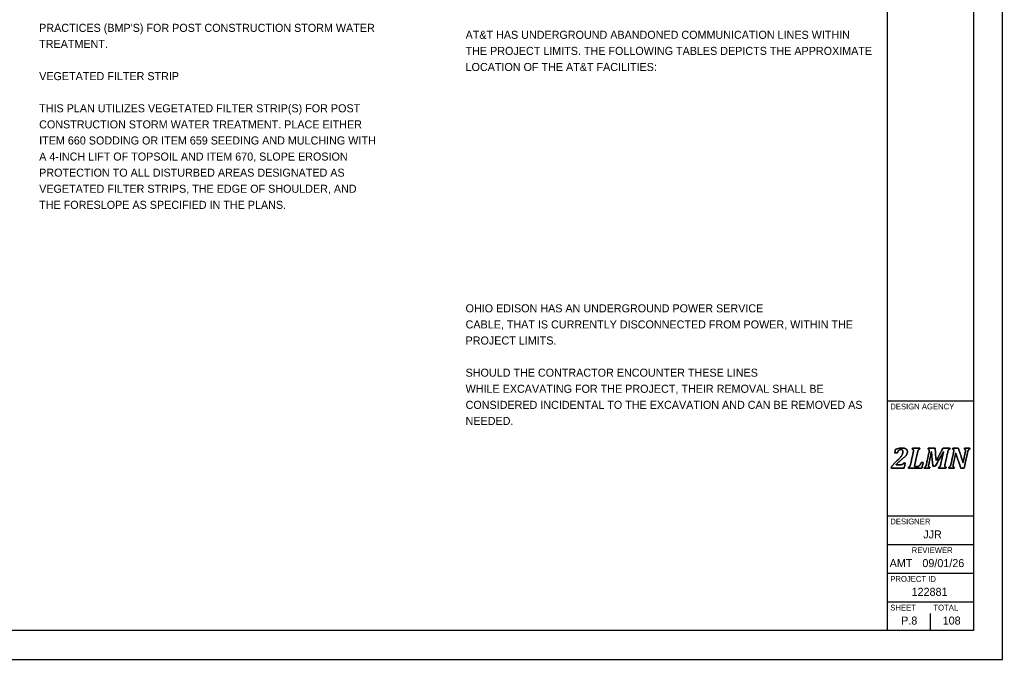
# Model space of a CAD drawing. Extents: x 0 to 34, y 0 to 22.
# Drawn here: x 16.9 to 34, y 0 to 11.13 of the extents above; entities that cross this region are included whole.
import ezdxf

# ---------------------------------------------------------------- set-up
doc = ezdxf.new("R2010")
doc.units = 0
for name, color, linetype in [('SH_Border', 7, 'Continuous'), ('SH_Cut_Line', 7, 'Continuous'), ('SH_Data', 7, 'Continuous'), ('SH_Text', 7, 'Continuous')]:
    doc.layers.add(name, color=color, linetype=linetype)

msp = doc.modelspace()

# ---------------------------------------------------------------- linework, layer by layer
at = {"layer": 'SH_Border'}
for p, q in [((32, 0.5), (32, 21.5)), ((32, 4.5), (33.5, 4.5)), ((32, 2.5), (33.5, 2.5)), ((32, 2), (33.5, 2)), ((32, 1.5), (33.5, 1.5)), ((32, 1), (33.5, 1))]:
    msp.add_line(p, q, dxfattribs=at)
msp.add_lwpolyline([(1.5, 21.5), (33.5, 21.5), (33.5, 0.5), (1.5, 0.5)], close=True, dxfattribs=at)
at = {"layer": 'SH_Cut_Line'}
msp.add_lwpolyline([(0, 0), (34, 0), (34, 22), (0, 22)], close=True, dxfattribs=at)
at = {"layer": 'SH_Data'}
for p, q in [((32.75, 3.5), (32.75, 3.5)), ((32.75, 0.5), (32.75, 0.8)), ((32.375, 0.675), (32.375, 0.675))]:
    msp.add_line(p, q, dxfattribs=at)
for points in [[(32.237, 3.388), (32.246, 3.388), (32.253, 3.389), (32.258, 3.39), (32.263, 3.392), (32.267, 3.394), (32.27, 3.397), (32.273, 3.401), (32.277, 3.408), (32.281, 3.417), (32.281, 3.417), (32.312, 3.417), (32.312, 3.417), (32.312, 3.417), (32.29, 3.326), (32.29, 3.326), (32.29, 3.326), (32.066, 3.326), (32.066, 3.326), (32.066, 3.326), (32.069, 3.343), (32.069, 3.343), (32.078, 3.358), (32.091, 3.375), (32.106, 3.394), (32.122, 3.412), (32.144, 3.435), (32.172, 3.462), (32.197, 3.486), (32.217, 3.506), (32.23, 3.521), (32.243, 3.537), (32.253, 3.551), (32.259, 3.566), (32.266, 3.58), (32.269, 3.595), (32.269, 3.61), (32.269, 3.622), (32.266, 3.632), (32.26, 3.64), (32.253, 3.647), (32.245, 3.65), (32.234, 3.65), (32.22, 3.65), (32.208, 3.646), (32.198, 3.636), (32.188, 3.627), (32.18, 3.613), (32.172, 3.593), (32.172, 3.593), (32.126, 3.593), (32.126, 3.593), (32.126, 3.593), (32.14, 3.654), (32.14, 3.654), (32.166, 3.663), (32.188, 3.669), (32.205, 3.673), (32.223, 3.676), (32.24, 3.678), (32.258, 3.678), (32.278, 3.678), (32.295, 3.675), (32.309, 3.669), (32.322, 3.664), (32.332, 3.656), (32.339, 3.646), (32.345, 3.637), (32.348, 3.626), (32.348, 3.613), (32.348, 3.602), (32.346, 3.591), (32.342, 3.581), (32.339, 3.571), (32.333, 3.56), (32.324, 3.549), (32.315, 3.539), (32.304, 3.526), (32.289, 3.513), (32.275, 3.499), (32.254, 3.482), (32.228, 3.46), (32.216, 3.45), (32.202, 3.438), (32.188, 3.425), (32.174, 3.412), (32.162, 3.4), (32.154, 3.391), (32.154, 3.391), (32.153, 3.388), (32.153, 3.388), (32.153, 3.388), (32.237, 3.388), (32.237, 3.388)], [(32.237, 3.388), (32.237, 3.388), (32.153, 3.388), (32.153, 3.388), (32.153, 3.388), (32.154, 3.391), (32.154, 3.391), (32.162, 3.4), (32.174, 3.412), (32.188, 3.425), (32.202, 3.438), (32.216, 3.45), (32.228, 3.46), (32.254, 3.482), (32.275, 3.499), (32.289, 3.513), (32.304, 3.526), (32.315, 3.539), (32.324, 3.549), (32.333, 3.56), (32.339, 3.571), (32.342, 3.581), (32.346, 3.591), (32.348, 3.602), (32.348, 3.613), (32.348, 3.626), (32.345, 3.637), (32.339, 3.646), (32.332, 3.656), (32.322, 3.664), (32.309, 3.669), (32.295, 3.675), (32.278, 3.678), (32.258, 3.678), (32.24, 3.678), (32.223, 3.676), (32.205, 3.673), (32.188, 3.669), (32.166, 3.663), (32.14, 3.654), (32.14, 3.654), (32.126, 3.593), (32.126, 3.593), (32.126, 3.593), (32.172, 3.593), (32.172, 3.593), (32.18, 3.613), (32.188, 3.627), (32.198, 3.636), (32.208, 3.646), (32.22, 3.65), (32.234, 3.65), (32.245, 3.65), (32.253, 3.647), (32.26, 3.64), (32.266, 3.632), (32.269, 3.622), (32.269, 3.61), (32.269, 3.595), (32.266, 3.58), (32.259, 3.566), (32.253, 3.551), (32.243, 3.537), (32.23, 3.521), (32.217, 3.506), (32.197, 3.486), (32.172, 3.462), (32.144, 3.435), (32.122, 3.412), (32.106, 3.394), (32.091, 3.375), (32.078, 3.358), (32.069, 3.343), (32.069, 3.343), (32.066, 3.326), (32.066, 3.326), (32.066, 3.326), (32.29, 3.326), (32.29, 3.326), (32.29, 3.326), (32.312, 3.417), (32.312, 3.417), (32.312, 3.417), (32.281, 3.417), (32.281, 3.417), (32.277, 3.408), (32.273, 3.401), (32.27, 3.397), (32.267, 3.394), (32.263, 3.392), (32.258, 3.39), (32.253, 3.389), (32.246, 3.388), (32.237, 3.388)], [(32.518, 3.356), (32.527, 3.356), (32.533, 3.357), (32.538, 3.358), (32.542, 3.36), (32.546, 3.362), (32.55, 3.365), (32.554, 3.368), (32.558, 3.372), (32.562, 3.377), (32.567, 3.382), (32.571, 3.388), (32.576, 3.397), (32.58, 3.405), (32.585, 3.415), (32.589, 3.427), (32.589, 3.427), (32.624, 3.427), (32.624, 3.427), (32.624, 3.427), (32.598, 3.326), (32.598, 3.326), (32.598, 3.326), (32.365, 3.326), (32.365, 3.326), (32.365, 3.326), (32.369, 3.343), (32.369, 3.343), (32.376, 3.345), (32.381, 3.348), (32.385, 3.351), (32.389, 3.355), (32.392, 3.36), (32.395, 3.366), (32.398, 3.373), (32.4, 3.382), (32.403, 3.395), (32.403, 3.395), (32.449, 3.605), (32.449, 3.605), (32.452, 3.615), (32.453, 3.625), (32.453, 3.635), (32.453, 3.642), (32.451, 3.647), (32.448, 3.651), (32.444, 3.654), (32.439, 3.656), (32.432, 3.657), (32.432, 3.657), (32.435, 3.674), (32.435, 3.674), (32.435, 3.674), (32.563, 3.674), (32.563, 3.674), (32.563, 3.674), (32.559, 3.657), (32.559, 3.657), (32.552, 3.655), (32.547, 3.652), (32.543, 3.649), (32.539, 3.645), (32.536, 3.64), (32.533, 3.634), (32.531, 3.627), (32.528, 3.618), (32.525, 3.605), (32.525, 3.605), (32.47, 3.356), (32.47, 3.356), (32.47, 3.356), (32.518, 3.356), (32.518, 3.356)], [(32.518, 3.356), (32.518, 3.356), (32.47, 3.356), (32.47, 3.356), (32.47, 3.356), (32.525, 3.605), (32.525, 3.605), (32.528, 3.618), (32.531, 3.627), (32.533, 3.634), (32.536, 3.64), (32.539, 3.645), (32.543, 3.649), (32.547, 3.652), (32.552, 3.655), (32.559, 3.657), (32.559, 3.657), (32.563, 3.674), (32.563, 3.674), (32.563, 3.674), (32.435, 3.674), (32.435, 3.674), (32.435, 3.674), (32.432, 3.657), (32.432, 3.657), (32.439, 3.656), (32.444, 3.654), (32.448, 3.651), (32.451, 3.647), (32.453, 3.642), (32.453, 3.635), (32.453, 3.625), (32.452, 3.615), (32.449, 3.605), (32.449, 3.605), (32.403, 3.395), (32.403, 3.395), (32.4, 3.382), (32.398, 3.373), (32.395, 3.366), (32.392, 3.36), (32.389, 3.355), (32.385, 3.351), (32.381, 3.348), (32.376, 3.345), (32.369, 3.343), (32.369, 3.343), (32.365, 3.326), (32.365, 3.326), (32.365, 3.326), (32.598, 3.326), (32.598, 3.326), (32.598, 3.326), (32.624, 3.427), (32.624, 3.427), (32.624, 3.427), (32.589, 3.427), (32.589, 3.427), (32.585, 3.415), (32.58, 3.405), (32.576, 3.397), (32.571, 3.388), (32.567, 3.382), (32.562, 3.377), (32.558, 3.372), (32.554, 3.368), (32.55, 3.365), (32.546, 3.362), (32.542, 3.36), (32.538, 3.358), (32.533, 3.357), (32.527, 3.356), (32.518, 3.356)], [(32.829, 3.674), (32.829, 3.674), (32.849, 3.461), (32.849, 3.461), (32.849, 3.461), (32.969, 3.674), (32.969, 3.674), (32.969, 3.674), (33.087, 3.674), (33.087, 3.674), (33.087, 3.674), (33.084, 3.657), (33.084, 3.657), (33.077, 3.655), (33.071, 3.652), (33.067, 3.649), (33.064, 3.645), (33.06, 3.64), (33.058, 3.634), (33.055, 3.627), (33.052, 3.618), (33.05, 3.605), (33.05, 3.605), (33.003, 3.395), (33.003, 3.395), (33.002, 3.39), (33.002, 3.387), (33.001, 3.384), (33.001, 3.382), (33.001, 3.379), (33, 3.376), (33, 3.373), (33, 3.369), (33, 3.365), (33, 3.358), (33.002, 3.353), (33.005, 3.349), (33.008, 3.346), (33.014, 3.344), (33.021, 3.343), (33.021, 3.343), (33.018, 3.326), (33.018, 3.326), (33.018, 3.326), (32.89, 3.326), (32.89, 3.326), (32.89, 3.326), (32.893, 3.343), (32.893, 3.343), (32.9, 3.345), (32.906, 3.348), (32.91, 3.351), (32.914, 3.355), (32.917, 3.36), (32.919, 3.366), (32.922, 3.373), (32.925, 3.382), (32.928, 3.395), (32.928, 3.395), (32.951, 3.502), (32.951, 3.502), (32.954, 3.513), (32.957, 3.529), (32.962, 3.548), (32.967, 3.568), (32.972, 3.588), (32.978, 3.609), (32.978, 3.609), (32.973, 3.609), (32.973, 3.609), (32.965, 3.594), (32.957, 3.579), (32.948, 3.563), (32.948, 3.563), (32.833, 3.364), (32.833, 3.364), (32.833, 3.364), (32.792, 3.364), (32.792, 3.364), (32.792, 3.364), (32.775, 3.518), (32.775, 3.518), (32.773, 3.537), (32.772, 3.554), (32.77, 3.569), (32.769, 3.583), (32.768, 3.597), (32.768, 3.611), (32.768, 3.611), (32.764, 3.611), (32.764, 3.611), (32.761, 3.596), (32.758, 3.578), (32.755, 3.558), (32.751, 3.538), (32.747, 3.521), (32.744, 3.507), (32.744, 3.507), (32.72, 3.395), (32.72, 3.395), (32.719, 3.39), (32.718, 3.387), (32.718, 3.384), (32.717, 3.382), (32.717, 3.379), (32.717, 3.376), (32.717, 3.373), (32.716, 3.369), (32.716, 3.365), (32.716, 3.358), (32.718, 3.353), (32.721, 3.349), (32.725, 3.346), (32.73, 3.344), (32.738, 3.343), (32.738, 3.343), (32.734, 3.326), (32.734, 3.326), (32.734, 3.326), (32.641, 3.326), (32.641, 3.326), (32.641, 3.326), (32.644, 3.343), (32.644, 3.343), (32.651, 3.345), (32.657, 3.348), (32.661, 3.351), (32.665, 3.355), (32.668, 3.36), (32.67, 3.366), (32.673, 3.373), (32.676, 3.382), (32.679, 3.395), (32.679, 3.395), (32.725, 3.605), (32.725, 3.605), (32.727, 3.615), (32.728, 3.625), (32.728, 3.635), (32.728, 3.642), (32.727, 3.647), (32.723, 3.651), (32.72, 3.654), (32.715, 3.656), (32.707, 3.657), (32.707, 3.657), (32.711, 3.674), (32.711, 3.674), (32.711, 3.674), (32.829, 3.674), (32.829, 3.674)], [(32.829, 3.674), (32.829, 3.674), (32.711, 3.674), (32.711, 3.674), (32.711, 3.674), (32.707, 3.657), (32.707, 3.657), (32.715, 3.656), (32.72, 3.654), (32.723, 3.651), (32.727, 3.647), (32.728, 3.642), (32.728, 3.635), (32.728, 3.625), (32.727, 3.615), (32.725, 3.605), (32.725, 3.605), (32.679, 3.395), (32.679, 3.395), (32.676, 3.382), (32.673, 3.373), (32.67, 3.366), (32.668, 3.36), (32.665, 3.355), (32.661, 3.351), (32.657, 3.348), (32.651, 3.345), (32.644, 3.343), (32.644, 3.343), (32.641, 3.326), (32.641, 3.326), (32.641, 3.326), (32.734, 3.326), (32.734, 3.326), (32.734, 3.326), (32.738, 3.343), (32.738, 3.343), (32.73, 3.344), (32.725, 3.346), (32.721, 3.349), (32.718, 3.353), (32.716, 3.358), (32.716, 3.365), (32.716, 3.369), (32.717, 3.373), (32.717, 3.376), (32.717, 3.379), (32.717, 3.382), (32.718, 3.384), (32.718, 3.387), (32.719, 3.39), (32.72, 3.395), (32.72, 3.395), (32.744, 3.507), (32.744, 3.507), (32.747, 3.521), (32.751, 3.538), (32.755, 3.558), (32.758, 3.578), (32.761, 3.596), (32.764, 3.611), (32.764, 3.611), (32.768, 3.611), (32.768, 3.611), (32.768, 3.597), (32.769, 3.583), (32.77, 3.569), (32.772, 3.554), (32.773, 3.537), (32.775, 3.518), (32.775, 3.518), (32.792, 3.364), (32.792, 3.364), (32.792, 3.364), (32.833, 3.364), (32.833, 3.364), (32.833, 3.364), (32.948, 3.563), (32.948, 3.563), (32.957, 3.579), (32.965, 3.594), (32.973, 3.609), (32.973, 3.609), (32.978, 3.609), (32.978, 3.609), (32.972, 3.588), (32.967, 3.568), (32.962, 3.548), (32.957, 3.529), (32.954, 3.513), (32.951, 3.502), (32.951, 3.502), (32.928, 3.395), (32.928, 3.395), (32.925, 3.382), (32.922, 3.373), (32.919, 3.366), (32.917, 3.36), (32.914, 3.355), (32.91, 3.351), (32.906, 3.348), (32.9, 3.345), (32.893, 3.343), (32.893, 3.343), (32.89, 3.326), (32.89, 3.326), (32.89, 3.326), (33.018, 3.326), (33.018, 3.326), (33.018, 3.326), (33.021, 3.343), (33.021, 3.343), (33.014, 3.344), (33.008, 3.346), (33.005, 3.349), (33.002, 3.353), (33, 3.358), (33, 3.365), (33, 3.369), (33, 3.373), (33, 3.376), (33.001, 3.379), (33.001, 3.382), (33.001, 3.384), (33.002, 3.387), (33.002, 3.39), (33.003, 3.395), (33.003, 3.395), (33.05, 3.605), (33.05, 3.605), (33.052, 3.618), (33.055, 3.627), (33.058, 3.634), (33.06, 3.64), (33.064, 3.645), (33.067, 3.649), (33.071, 3.652), (33.077, 3.655), (33.084, 3.657), (33.084, 3.657), (33.087, 3.674), (33.087, 3.674), (33.087, 3.674), (32.969, 3.674), (32.969, 3.674), (32.969, 3.674), (32.849, 3.461), (32.849, 3.461), (32.849, 3.461), (32.829, 3.674), (32.829, 3.674)], [(33.137, 3.674), (33.137, 3.674), (33.234, 3.674), (33.234, 3.674), (33.234, 3.674), (33.283, 3.53), (33.283, 3.53), (33.296, 3.49), (33.307, 3.456), (33.315, 3.426), (33.315, 3.426), (33.318, 3.426), (33.318, 3.426), (33.323, 3.455), (33.329, 3.488), (33.337, 3.523), (33.337, 3.523), (33.355, 3.605), (33.355, 3.605), (33.357, 3.615), (33.358, 3.625), (33.358, 3.635), (33.358, 3.642), (33.357, 3.647), (33.353, 3.651), (33.35, 3.654), (33.345, 3.656), (33.337, 3.657), (33.337, 3.657), (33.341, 3.674), (33.341, 3.674), (33.341, 3.674), (33.434, 3.674), (33.434, 3.674), (33.434, 3.674), (33.431, 3.657), (33.431, 3.657), (33.424, 3.655), (33.418, 3.652), (33.414, 3.649), (33.41, 3.645), (33.407, 3.64), (33.405, 3.634), (33.402, 3.627), (33.399, 3.618), (33.396, 3.605), (33.396, 3.605), (33.335, 3.326), (33.335, 3.326), (33.335, 3.326), (33.277, 3.326), (33.277, 3.326), (33.277, 3.326), (33.216, 3.504), (33.216, 3.504), (33.211, 3.518), (33.207, 3.531), (33.204, 3.543), (33.2, 3.556), (33.195, 3.571), (33.19, 3.59), (33.19, 3.59), (33.186, 3.59), (33.186, 3.59), (33.185, 3.579), (33.182, 3.563), (33.179, 3.543), (33.175, 3.523), (33.17, 3.501), (33.165, 3.478), (33.165, 3.478), (33.147, 3.395), (33.147, 3.395), (33.146, 3.39), (33.145, 3.387), (33.145, 3.384), (33.144, 3.382), (33.144, 3.379), (33.144, 3.376), (33.143, 3.373), (33.143, 3.369), (33.143, 3.365), (33.143, 3.358), (33.145, 3.353), (33.148, 3.349), (33.152, 3.346), (33.157, 3.344), (33.164, 3.343), (33.164, 3.343), (33.161, 3.326), (33.161, 3.326), (33.161, 3.326), (33.067, 3.326), (33.067, 3.326), (33.067, 3.326), (33.071, 3.343), (33.071, 3.343), (33.078, 3.345), (33.083, 3.348), (33.087, 3.351), (33.091, 3.355), (33.094, 3.36), (33.097, 3.366), (33.1, 3.373), (33.102, 3.382), (33.105, 3.395), (33.105, 3.395), (33.151, 3.605), (33.151, 3.605), (33.154, 3.615), (33.155, 3.625), (33.155, 3.635), (33.155, 3.642), (33.153, 3.647), (33.15, 3.651), (33.146, 3.654), (33.141, 3.656), (33.134, 3.657), (33.134, 3.657), (33.137, 3.674), (33.137, 3.674)], [(33.137, 3.674), (33.137, 3.674), (33.134, 3.657), (33.134, 3.657), (33.141, 3.656), (33.146, 3.654), (33.15, 3.651), (33.153, 3.647), (33.155, 3.642), (33.155, 3.635), (33.155, 3.625), (33.154, 3.615), (33.151, 3.605), (33.151, 3.605), (33.105, 3.395), (33.105, 3.395), (33.102, 3.382), (33.1, 3.373), (33.097, 3.366), (33.094, 3.36), (33.091, 3.355), (33.087, 3.351), (33.083, 3.348), (33.078, 3.345), (33.071, 3.343), (33.071, 3.343), (33.067, 3.326), (33.067, 3.326), (33.067, 3.326), (33.161, 3.326), (33.161, 3.326), (33.161, 3.326), (33.164, 3.343), (33.164, 3.343), (33.157, 3.344), (33.152, 3.346), (33.148, 3.349), (33.145, 3.353), (33.143, 3.358), (33.143, 3.365), (33.143, 3.369), (33.143, 3.373), (33.144, 3.376), (33.144, 3.379), (33.144, 3.382), (33.145, 3.384), (33.145, 3.387), (33.146, 3.39), (33.147, 3.395), (33.147, 3.395), (33.165, 3.478), (33.165, 3.478), (33.17, 3.501), (33.175, 3.523), (33.179, 3.543), (33.182, 3.563), (33.185, 3.579), (33.186, 3.59), (33.186, 3.59), (33.19, 3.59), (33.19, 3.59), (33.195, 3.571), (33.2, 3.556), (33.204, 3.543), (33.207, 3.531), (33.211, 3.518), (33.216, 3.504), (33.216, 3.504), (33.277, 3.326), (33.277, 3.326), (33.277, 3.326), (33.335, 3.326), (33.335, 3.326), (33.335, 3.326), (33.396, 3.605), (33.396, 3.605), (33.399, 3.618), (33.402, 3.627), (33.405, 3.634), (33.407, 3.64), (33.41, 3.645), (33.414, 3.649), (33.418, 3.652), (33.424, 3.655), (33.431, 3.657), (33.431, 3.657), (33.434, 3.674), (33.434, 3.674), (33.434, 3.674), (33.341, 3.674), (33.341, 3.674), (33.341, 3.674), (33.337, 3.657), (33.337, 3.657), (33.345, 3.656), (33.35, 3.654), (33.353, 3.651), (33.357, 3.647), (33.358, 3.642), (33.358, 3.635), (33.358, 3.625), (33.357, 3.615), (33.355, 3.605), (33.355, 3.605), (33.337, 3.523), (33.337, 3.523), (33.329, 3.488), (33.323, 3.455), (33.318, 3.426), (33.318, 3.426), (33.315, 3.426), (33.315, 3.426), (33.307, 3.456), (33.296, 3.49), (33.283, 3.53), (33.283, 3.53), (33.234, 3.674), (33.234, 3.674), (33.234, 3.674), (33.137, 3.674), (33.137, 3.674)]]:
    msp.add_open_spline(points, degree=3, dxfattribs=at)

# ---------------------------------------------------------------- texts
for s, height, p in [('DESIGN AGENCY', 0.1, (32.05, 4.35)), ('DESIGNER', 0.1, (32.05, 2.35)), ('JJR', 0.14, (32.624, 2.105)), ('REVIEWER', 0.1, (32.422, 1.85)), ('AMT', 0.14, (32.039, 1.605)), ('09/01/26', 0.14, (32.609, 1.605)), ('PROJECT ID', 0.1, (32.05, 1.35)), ('122881', 0.14, (32.421, 1.105)), ('SHEET', 0.1, (32.05, 0.85)), ('TOTAL', 0.1, (32.8, 0.85)), ('P.8', 0.14, (32.239, 0.605)), ('108', 0.14, (32.962, 0.605))]:
    msp.add_text(s, height=height, dxfattribs=at).set_placement(p)
at = {"layer": 'SH_Text'}
for s, p in [("PRACTICES (BMP'S) FOR POST CONSTRUCTION STORM WATER", (17.24, 10.92)), ('TREATMENT.', (17.24, 10.64)), ('AT&T HAS UNDERGROUND ABANDONED COMMUNICATION LINES WITHIN ', (24.66, 10.799)), ('THE PROJECT LIMITS. THE FOLLOWING TABLES DEPICTS THE APPROXIMATE', (24.66, 10.519)), ('LOCATION OF THE AT&T FACILITIES:', (24.66, 10.239)), ('VEGETATED FILTER STRIP', (17.24, 10.08)), ('THIS PLAN UTILIZES VEGETATED FILTER STRIP(S) FOR POST', (17.24, 9.52)), ('CONSTRUCTION STORM WATER TREATMENT. PLACE EITHER', (17.24, 9.24)), ('ITEM 660 SODDING OR ITEM 659 SEEDING AND MULCHING WITH', (17.24, 8.96)), ('A 4-INCH LIFT OF TOPSOIL AND ITEM 670, SLOPE EROSION', (17.24, 8.68)), ('PROTECTION TO ALL DISTURBED AREAS DESIGNATED AS', (17.24, 8.4)), ('VEGETATED FILTER STRIPS, THE EDGE OF SHOULDER, AND', (17.24, 8.12)), ('THE FORESLOPE AS SPECIFIED IN THE PLANS.', (17.24, 7.84)), ('OHIO EDISON HAS AN UNDERGROUND POWER SERVICE', (24.66, 6.039)), ('CABLE, THAT IS CURRENTLY DISCONNECTED FROM POWER, WITHIN THE', (24.66, 5.759)), ('PROJECT LIMITS.', (24.66, 5.479)), ('SHOULD THE CONTRACTOR ENCOUNTER THESE LINES', (24.66, 4.919)), ('WHILE EXCAVATING FOR THE PROJECT, THEIR REMOVAL SHALL BE ', (24.66, 4.639)), ('CONSIDERED INCIDENTAL TO THE EXCAVATION AND CAN BE REMOVED AS ', (24.66, 4.359)), ('NEEDED.', (24.66, 4.079))]:
    msp.add_text(s, height=0.14, dxfattribs=at).set_placement(p)

doc.saveas('drawing.dxf')
